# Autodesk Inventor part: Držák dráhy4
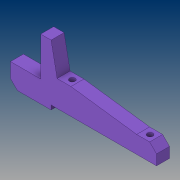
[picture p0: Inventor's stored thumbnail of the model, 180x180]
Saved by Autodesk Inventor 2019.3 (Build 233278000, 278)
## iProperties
Created: 2019-03
Part Number: Držák dráhy4
Material: Ocel, měkká, svařovaná
Document SubType Name: Modeling
Designer: B-hon
Density: 7.85 g/cm^3
Appearance: Fialová
Mass: 605.012 g
Surface Area: 186.842 cm^2
Volume: 77.0716 cm^3
Author: B-hon
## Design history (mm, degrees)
sketch "Náčrt1"
  geometry: L1 (0, 1)-(0, 45); L2 (0, 0)-(44, 0); L3 (0, 45)-(12, 45); L4 (12, 45)-(19, 10); L5 (-1, 0)-(-34.961, 0); L6 (-34.961, 0)-(-34.961, -25); L7 (132, -20)-(132, 0); L8 (117, -34.12)-(27, -34.12); L9 (19, 10)-(35, 10); L10 (35, 10)-(111, 0); L11 (111, 0)-(132, 0); L12 (-34.961, -25)-(12, -25); L13 (12, -25)-(12, -20); L14 (12, -20)-(132, -20); A1 r 1 centre (-1, 1) between (-1, 0) and (0, 1)
  constraints: 28 end point, 7 horizontal, 4 perpendicular, 2 point on circle, 2 point on line, 2 tangent, 1 centre point, 1 vertical
  dimensions: "d0" = 45 distance of L2.start L1.end; "d1" = 90 deg angle of L2 L1 (derived); "d5" = 132 distance from line of L7.end L1; "d6" = 34.961 distance of L2.start L5.end; "d7" = 25 distance of L5.end L6.end; "d8" = 90 distance of L8.start L8.end; "d9" = 15 distance from line of L7 L8.start; "d11" = 12 distance of L1.end L3.end; "d12" = 8 horizontal distance of L8.end L4.end; "d13" = 8 horizontal distance of L8.end L9.end; "d22" = 6 horizontal distance of L8.start L10.end; "d25" = 1 radius of A1; "d26" = 15 distance from line of L8.end L13
extrude "Vysunutí1" new body sketch "Náčrt1" distance "d14" = 15; taper "d15" = 0 deg
chamfer "Zkosení1" distance "d27" = 6; stored, may be unused: second distance "d28" = 2, angle "d29" = 45 deg
chamfer "Zkosení2" distance "d30" = 8; stored, may be unused: second distance "d31" = 2, angle "d32" = 45 deg
sketch "Náčrt3"
  geometry: L1 (0, 15)-(120, 15) reference; L2 (120, 0)-(120, 15) reference; 3 further points
  dimensions: "d33" = 7.5 distance from line of L1 point (17, 7.5); "d34" = 90 distance of point (107, 7.5) point (17, 7.5); "d35" = 13 distance from line of L2 point (107, 7.5); "d36" = 7.5 distance from line of L1 point (107, 7.5)
hole "Díra1" sketch "Náčrt3" at (17, 7.5), (107, 7.5) diameter "d37" = 6.5; stored, may be unused: countersink angle "d41" = 90 deg, drill point angle "d43" = 118 deg; dims "d38" = 6, "d39" = 4, "d40" = 2, "d42" = 8
node "Upravit přímo1"
node "Těleso1"
feature "Posunout1" dims "d46" = 2
other parameters: "sa_0" = 0, "sa_1" = -1000000, "sa_2" = 0, "d44" = 0, "d45" = 0
